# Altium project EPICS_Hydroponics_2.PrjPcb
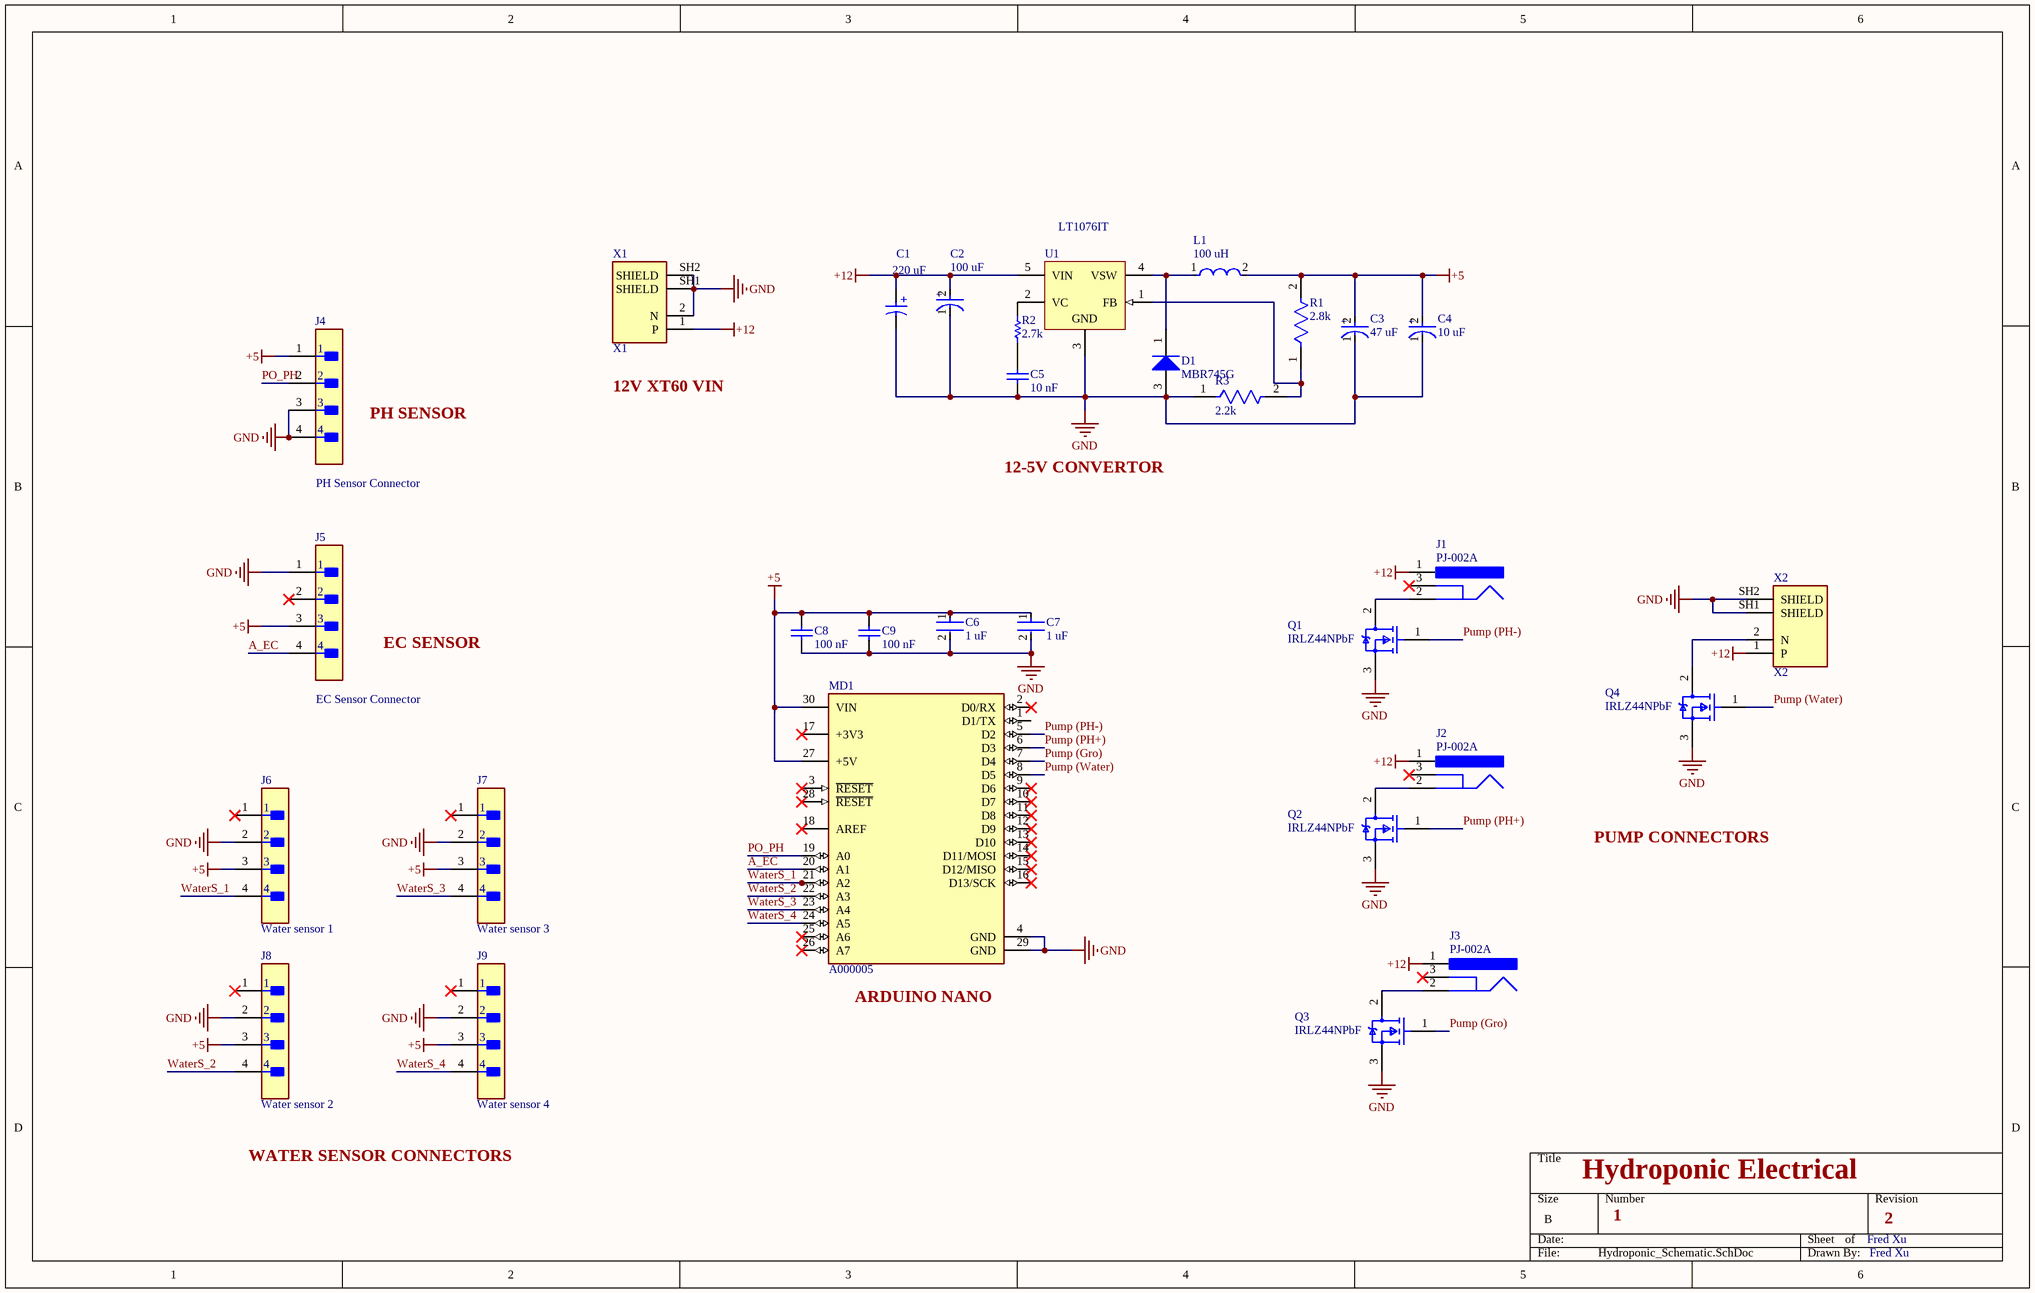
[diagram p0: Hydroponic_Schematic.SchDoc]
1 sheet, 31 parts. Net scope: global (net labels, ports and power ports of the same name join across sheets).
Board file: Hydroponic_PCB.PcbDoc

## Sheet Hydroponic_Schematic.SchDoc
size B; SheetNumber: 1; SheetTotal: 1

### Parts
C1  220 uF  [WCAP-ASLL_D6.3H7.7]
C2  100 uF  [FP-TGV10X10_5-MFG]
C3  47 uF  [FP-UUX1H470MNL6GS-MFG]
C4  10 uF  [FP-EDK9B-MFG]
C5  10 nF  [CAPC1608X87X35LL15T15]
C6  1 uF  [FP-CC0805-0_85-MFG]
C7  1 uF  [FP-CC0805-0_85-MFG]
C8  100 nF  [CAPC2013X140X50LL20T25]
C9  100 nF  [CAPC2013X140X50LL20T25]
D1  MBR745G  [ONSC-TO-220-2-221B-04_E]
J1  PJ-002A  [CUI-PJ-002A_V]
J2  PJ-002A  [CUI-PJ-002A_V]
J3  PJ-002A  [CUI-PJ-002A_V]
J4  PH Sensor Connector  [FP-B4B-XH-AM_LF_SN-MFG]
J5  EC Sensor Connector  [FP-B4B-XH-AM_LF_SN-MFG]
J6  Water sensor 1  [FP-B4B-XH-AM_LF_SN-MFG]
J7  Water sensor 3  [FP-B4B-XH-AM_LF_SN-MFG]
J8  Water sensor 2  [FP-B4B-XH-AM_LF_SN-MFG]
J9  Water sensor 4  [FP-B4B-XH-AM_LF_SN-MFG]
L1  100 uH  [FP-LQM21DH_70-IPC_C]
MD1  A000005  [FP-A000005-MFG]
Q1  IRLZ44NPbF  [FP-PG-TO220-3-MFG]
Q2  IRLZ44NPbF  [FP-PG-TO220-3-MFG]
Q3  IRLZ44NPbF  [FP-PG-TO220-3-MFG]
Q4  IRLZ44NPbF  [FP-PG-TO220-3-MFG]
R1  2.8k  [FP-RG2012-IPC_C]
R2  2.7k  [RESC0603(1608)_M]
R3  2.2k  [FP-AC0805-MFG]
U1  LT1076IT  [LT-T-5-S]
X1  X1  [PCBComponent_1]
X2  X2  [PCBComponent_1]

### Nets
+5: C3.2(A) C4.2(A) C6.1 C7.1 C8.2 C9.2 J4.1 J5.3 J6.3 J7.3 J8.3 J9.3 L1.2 MD1.27(+5V) MD1.30(VIN) R1.2
+12: C1.1(P) C2.2(A) J1.1 J2.1 J3.1 U1.5(VIN) X1.1(P) X2.1(P)
GND: C1.2(N) C2.1(C) C3.1(C) C4.1(C) C5.2 C6.2 C7.2 C8.1 C9.1 D1.3(A) J4.3 J4.4 J5.1 J6.2 J7.2 J8.2 J9.2 MD1.4(GND) MD1.29(GND) Q1.3(S) Q2.3(S) Q3.3(S) Q4.3(S) R3.1 U1.3(GND) X1.2(N) X1.SH1(SHIELD) X1.SH2(SHIELD) X2.SH1(SHIELD) X2.SH2(SHIELD)
A_EC: J5.4 MD1.20(A1)
PO_PH: J4.2 MD1.19(A0)
Pump (Gro): MD1.7(D4) Q3.1(G)
Pump (PH+): MD1.6(D3) Q2.1(G)
Pump (PH-): MD1.5(D2) Q1.1(G)
Pump (Water): MD1.8(D5) Q4.1(G)
WaterS_1: J6.4 MD1.21(A2)
WaterS_2: J8.4 MD1.22(A3)
WaterS_3: J7.4 MD1.23(A4)
WaterS_4: J9.4 MD1.24(A5)
NetC5_1: C5.1 R2.1
NetD1_1: D1.1(K) L1.1 U1.4(VSW)
NetJ1_2: J1.2 Q1.2(D)
NetJ2_2: J2.2 Q2.2(D)
NetJ3_2: J3.2 Q3.2(D)
NetQ4_2: Q4.2(D) X2.2(N)
NetR1_1: R1.1 R3.2 U1.1(FB)
NetR2_2: R2.2 U1.2(VC)

Not connected (* = marked no-connect by the designer): J1 3*; J2 3*; J3 3*; J5 2*; J6 1*; J7 1*; J8 1*; J9 1*; MD1 1(D1/TX) 2(D0/RX)* 3(~{RESET})* 9(D6)* 10(D7)* 11(D8)* 12(D9)* 13(D10)* 14(D11/MOSI)* 15(D12/MISO)* 16(D13/SCK)* 17(+3V3)* 18(AREF)* 25(A6)* 26(A7)* 28(~{RESET})*

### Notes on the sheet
- PH SENSOR
- (near X1) 12V XT60 VIN
- 12-5V CONVERTOR
- EC SENSOR
- PUMP CONNECTORS
- (near MD1) ARDUINO NANO
- WATER SENSOR CONNECTORS
- Hydroponic Electrical
- 1
- Fred Xu
- 2

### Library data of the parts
C1 = CMP-03913-53914500-3: Ripple Current: 280mA; ESR (Equivalent Series Resistance): 246.927mΩ; Life (Hours): 2000hours; Material: Aluminium; Polarity: Polar; Insulation Resistance: 454.545kΩ; Impedance: 360mΩ; Leakage Current: 13.86µA; Voltage Rating: 6.3V; Tolerance: 20%; Capacitance: 220µF
C2 = CMP-35376-000017-1: CAP ALUM 100UF 20% 35V SMD
C3 = CMP-12462-000056-1: CAP ALUM 47UF 20% 50V SMD; Ripple Current: 167mA; Dissipation Factor: 0.1%; Leakage Current: 70.5uA; Life (Hours): 2000Hour; Lead Diameter: 1.1mm
C4 = CMP-03015-000003-1: CAP ALUM 10UF 20% 35V SMD; Manufacturer: Kemet; Manufacturer Part Number: EDK106M035A9BAA; Dissipation Factor: 16%; Material: Aluminum; Leakage Current: 3.5uA; Ripple Current: 24mA; Life: 2000Hours
C5 = CMP-2006-03842-1: Manufacturer: Kemet; Part Number: C0603S103K4RACTU
C6 C7 = CMP-03422-000746-1: CAP CER 1UF 10V X5R 0805; Manufacturer: Yageo; Manufacturer Part Number: CC0805KKX5R6BB105; Material: Ceramic; Tolerance: 0.1
C8 C9 = CMP-2007-04740-1: Part Number: 08051C104M4Z2A; Manufacturer: AVX Interconnect / Elco
D1 = CMP-1055-00593-1: SWITCHMODE(TM) Power Rectifier, 2-Pin TO-220, Pb-Free, Tube; Manufacturer: On Semiconductor; IFSM Max (A): 150; Configuration: Single
J1-J3 = CMP-2000-06895-2: Through Hole Right Angle DC Power Jack, 2.5 A, 2 mm Center Pin, 3 Position, -25 to 85 degC, RoHS, Bulk; Manufacturer: CUIInc.; Brand: CUI; Inside Contact Diameter: 2mm; Voltage Rating: 24V; Outside Contact Diameter: 6.5mm; Current Rating: 2.5A; Insulation Resistance: 50MOhms
J4-J9 = CMP-17439-000117-1: CONN HEADER VERT 4POS 2.5MM; Max Current Rating: 3A; Gender: Male; Contact Resistance: 20mR; Number of Positions: 4; Mated Stacking Heights: 9.8mm; Voltage Rating: 250V
L1 = CMP-06042-017057-1: Multilayer type Inductor for Power Lines for Automotive 100uH ±20% @1MHz, 160mA, Max DCR 4.095Ω, SRF 8MHz
MD1 = CMP-189986-000002-1: ARDUINO NANO ATMEGA328 EVAL BRD; Number of Bits: 8; Evaluation Kit: Yes; Operating Supply Voltage: 12V; Interface: I2C; Data Bus Width: 8b; Core Architecture: AVR
Q1-Q4 = CMP-32901-000488-1: MOSFET N-CH 55V 47A TO220AB; Turn-On Delay Time: 11ns; Gate to Source Voltage (Vgs): 16V; Element Configuration: Single; Rds On Max: 22mR; Turn-Off Delay Time: 26ns; Max Power Dissipation: 110W; Threshold Voltage: 2V; Drain to Source Resistance: 35mR; Input Capacitance: 1.7nF
R1 = CMP-28537-010746-1: Automotive Metal Thin Film Chip Resistor, 0805, 2.8kΩ, 0.1%, 25ppm/°C, 0.125W, 150V; Resistance: 2.8kR; Power Rating: 125mW
R2 = CMP-1012-00084-1: 2K7 0.1W 5% 0603 (1608 Metric)  SMD; Case-EIA: 0603; Value: 2700.00 Ohm; Case-Metric: 1608
R3 = CMP-03412-037614-1: RES SMD 2.2K OHM 5% 1/8W 0805; Manufacturer Part Number: AC0805JR-072K2L; Manufacturer: Yageo; Voltage Rating: 150V; Value: 2.2KΩ; Automotive Grade: Grade 0; Tolerance: 0.05
U1 = CMP-0491-02059-1: Step-Down Switching Regulator, 5-pin FM (T-5), -40 to 85 degC; Manufacturer: Linear Technology; Number of Outputs: 1
X1 X2 = xt60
